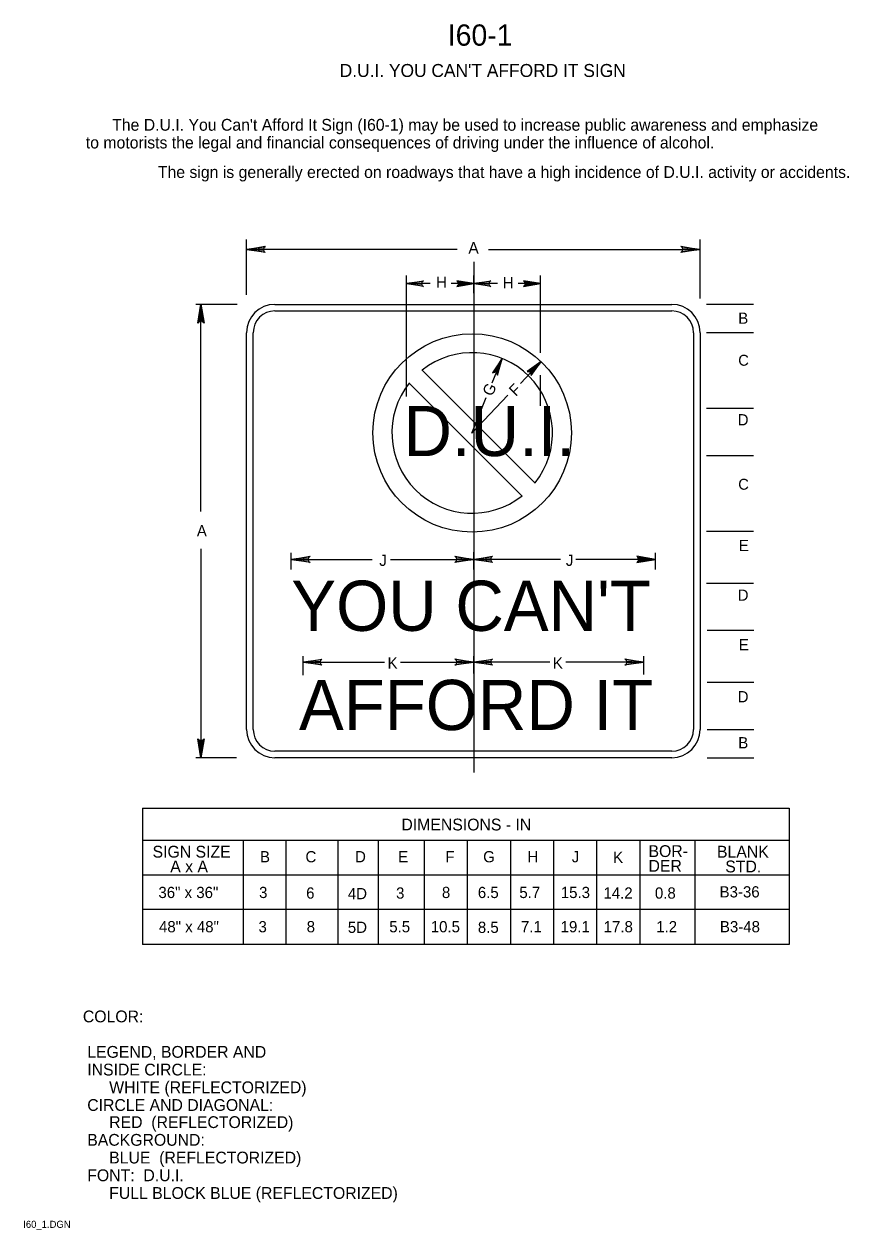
# Model space of a CAD drawing. Extents: x 0.013 to 0.187, y 0.004 to 0.259.
import ezdxf

# ---------------------------------------------------------------- set-up
doc = ezdxf.new("R2010")
doc.units = 0
doc.layers.add('1', color=7, linetype='Continuous')
doc.layers.add('3', color=7, linetype='Continuous')

# ---------------------------------------------------------------- blocks, each defined once
blk = doc.blocks.new('RARROW')
at = {"layer": '3'}
for p, q in [((-2.156, 0.28500000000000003), (-2.2665, 0.384625)), ((-2.2665, 0.384625), (0, 0)), ((0, 0), (-2.2665, -0.379125)), ((-2.156, 0.28500000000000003), (-2.075625, 0.12075)), ((0, 0), (-2.156, 0.28500000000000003)), ((-2.14975, -0.2705), (0, 0)), ((-2.075625, 0.12075), (0, 0)), ((0, 0), (-2.074, -0.108)), ((-2.2665, -0.379125), (-2.14975, -0.2705)), ((-2.074, -0.108), (-2.14975, -0.2705))]:
    blk.add_line(p, q, dxfattribs=at)

msp = doc.modelspace()

# ---------------------------------------------------------------- linework, layer by layer
at = {"layer": '1'}
for p, q in [((0.107875, 0.208875), (0.107875, 0.10075)), ((0.096875, 0.186), (0.120875, 0.162)), ((0.094125, 0.18325), (0.11812500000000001, 0.15925))]:
    msp.add_line(p, q, dxfattribs=at)
msp.add_circle((0.10754158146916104, 0.172648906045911), 0.021, dxfattribs=at)
for start, end in [(321.56815, 128.43185), (141.56815, 308.43185)]:
    msp.add_arc((0.10754158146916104, 0.172648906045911), 0.017, start, end, dxfattribs=at)
at = {"layer": '3'}
for p, q in [((0.059754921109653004, 0.20187213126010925), (0.059754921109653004, 0.21362213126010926)), ((0.15579158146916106, 0.20112213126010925), (0.15579158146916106, 0.21362213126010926)), ((0.104375, 0.2115), (0.059750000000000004, 0.2115)), ((0.111, 0.2115), (0.15575, 0.2115)), ((0.15579158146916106, 0.20149713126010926), (0.15579158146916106, 0.21012213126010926)), ((0.093625, 0.180375), (0.093625, 0.20600000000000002)), ((0.098625, 0.20425000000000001), (0.093625, 0.20425000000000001)), ((0.107875, 0.20425000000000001), (0.10312500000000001, 0.20425000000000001)), ((0.107875, 0.20225), (0.107875, 0.20600000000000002)), ((0.112875, 0.20425000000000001), (0.107875, 0.20425000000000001)), ((0.122, 0.20425000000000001), (0.11725000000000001, 0.20425000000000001)), ((0.122, 0.18962500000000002), (0.122, 0.20600000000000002)), ((0.05780174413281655, 0.19987213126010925), (0.049041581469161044, 0.19987213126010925)), ((0.050125, 0.156), (0.050125, 0.199875)), ((0.06579158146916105, 0.19987213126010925), (0.14979158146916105, 0.19987213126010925)), ((0.15712500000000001, 0.199875), (0.167125, 0.199875)), ((0.06579158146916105, 0.1984721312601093), (0.14979158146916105, 0.1984721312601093)), ((0.05979158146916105, 0.10987213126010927), (0.05979158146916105, 0.19387213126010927)), ((0.06119158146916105, 0.10987213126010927), (0.06119158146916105, 0.19387213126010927)), ((0.1543915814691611, 0.19387213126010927), (0.1543915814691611, 0.10987213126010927)), ((0.15579158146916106, 0.19387213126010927), (0.15579158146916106, 0.10987213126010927)), ((0.15712500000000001, 0.193875), (0.167125, 0.193875)), ((0.11175, 0.18325), (0.113875, 0.18837500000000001)), ((0.11775000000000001, 0.183125), (0.122125, 0.18775)), ((0.122, 0.178375), (0.122, 0.184875)), ((0.1075, 0.172625), (0.115125, 0.180625)), ((0.1075, 0.172625), (0.1105, 0.180125)), ((0.15712500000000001, 0.177875), (0.167125, 0.177875)), ((0.15712500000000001, 0.167875), (0.167125, 0.167875)), ((0.15712500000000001, 0.151875), (0.167125, 0.151875)), ((0.050125, 0.148125), (0.050125, 0.10387500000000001)), ((0.06925, 0.14375000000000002), (0.06925, 0.14725)), ((0.06925, 0.145875), (0.08637500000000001, 0.145875)), ((0.09025, 0.145875), (0.107875, 0.145875)), ((0.107875, 0.14375000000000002), (0.107875, 0.147375)), ((0.12625, 0.145875), (0.107875, 0.145875)), ((0.146375, 0.145875), (0.1295, 0.145875)), ((0.146375, 0.14375000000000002), (0.146375, 0.14725)), ((0.15712500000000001, 0.140875), (0.167125, 0.140875)), ((0.15729158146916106, 0.13087213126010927), (0.16716658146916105, 0.13087213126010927)), ((0.07175000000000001, 0.121375), (0.07175000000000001, 0.12537500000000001)), ((0.107875, 0.12175), (0.107875, 0.12537500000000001)), ((0.143875, 0.1215), (0.143875, 0.12537500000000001)), ((0.07175000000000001, 0.124125), (0.089, 0.124125)), ((0.092375, 0.124125), (0.107875, 0.124125)), ((0.124, 0.124125), (0.107875, 0.124125)), ((0.143875, 0.124125), (0.12737500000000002, 0.124125)), ((0.15729158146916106, 0.11987213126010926), (0.16716658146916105, 0.11987213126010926)), ((0.15729158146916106, 0.10987213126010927), (0.16716658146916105, 0.10987213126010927)), ((0.14979158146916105, 0.10527213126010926), (0.06579158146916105, 0.10527213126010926)), ((0.057666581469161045, 0.10387213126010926), (0.049041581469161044, 0.10387213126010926)), ((0.14979158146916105, 0.10387213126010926), (0.06579158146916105, 0.10387213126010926)), ((0.15729158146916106, 0.10387213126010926), (0.16716658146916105, 0.10387213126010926)), ((0.03775, 0.09325), (0.03775, 0.064375)), ((0.037761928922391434, 0.09325), (0.17463692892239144, 0.09325)), ((0.174625, 0.09325), (0.174625, 0.064375)), ((0.17463692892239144, 0.08637500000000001), (0.037761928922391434, 0.08637500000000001)), ((0.05905351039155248, 0.08637213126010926), (0.05905351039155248, 0.06437213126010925)), ((0.068125, 0.08637500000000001), (0.068125, 0.064375)), ((0.079125, 0.08637500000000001), (0.079125, 0.064375)), ((0.08762500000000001, 0.08637500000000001), (0.08762500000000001, 0.064375)), ((0.097375, 0.08637500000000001), (0.097375, 0.064375)), ((0.1065, 0.08637500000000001), (0.1065, 0.064375)), ((0.115625, 0.08637500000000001), (0.115625, 0.064375)), ((0.12475, 0.08637500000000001), (0.12475, 0.064375)), ((0.133875, 0.08637500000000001), (0.133875, 0.064375)), ((0.14305351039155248, 0.08637213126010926), (0.14305351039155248, 0.06437213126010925)), ((0.15467851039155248, 0.08637213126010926), (0.15467851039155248, 0.06437213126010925)), ((0.17463692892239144, 0.079), (0.037761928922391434, 0.079)), ((0.17463692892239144, 0.07175000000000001), (0.037761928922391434, 0.07175000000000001)), ((0.17463692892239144, 0.064375), (0.037761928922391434, 0.064375))]:
    msp.add_line(p, q, dxfattribs=at)
for centre, radius, start, end in [((0.06579158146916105, 0.1938721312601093), 0.006, 90, 180), ((0.14979158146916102, 0.1938721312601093), 0.006, 0, 90), ((0.06579158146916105, 0.1938721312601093), 0.0046, 90, 180), ((0.14979158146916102, 0.1938721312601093), 0.0046, 0, 90), ((0.06579158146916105, 0.1098721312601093), 0.006, 180, 270), ((0.06579158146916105, 0.1098721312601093), 0.0046, 180, 270), ((0.14979158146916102, 0.1098721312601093), 0.006, 270, 0), ((0.14979158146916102, 0.1098721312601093), 0.0046, 270, 0)]:
    msp.add_arc(centre, radius, start, end, dxfattribs=at)

# ---------------------------------------------------------------- block references
for p, xscale, yscale, rotation in [((0.059750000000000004, 0.2115), 0.0017647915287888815, 0.0017457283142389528, 180), ((0.093625, 0.20425000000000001), 0.0015883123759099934, 0.0015711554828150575, 180), ((0.107875, 0.20425000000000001), 0.0015883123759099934, 0.0015711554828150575, 180), ((0.050125, 0.199875), 0.0017647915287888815, 0.0017457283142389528, 90), ((0.113875, 0.18837500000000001), 0.0015883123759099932, -0.0015711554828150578, 65), ((0.122125, 0.18775), 0.0015883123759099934, -0.0015711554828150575, 44.99999999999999), ((0.06925, 0.145875), 0.0017647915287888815, 0.0017457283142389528, 180), ((0.107875, 0.145875), 0.0017647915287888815, 0.0017457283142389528, 180), ((0.07175000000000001, 0.124125), 0.0017647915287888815, 0.0017457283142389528, 180), ((0.107875, 0.124125), 0.0017647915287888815, 0.0017457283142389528, 180), ((0.050125, 0.10387500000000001), 0.0017647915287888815, 0.0017457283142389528, -90.00000000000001)]:
    msp.add_blockref('RARROW', p, dxfattribs=dict(at, xscale=xscale, yscale=yscale, rotation=rotation))
for p, xscale, yscale in [((0.15575, 0.2115), 0.0017647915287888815, 0.0017457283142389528), ((0.107875, 0.20425000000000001), 0.0015883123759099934, -0.0015711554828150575), ((0.122, 0.20425000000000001), 0.0015883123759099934, -0.0015711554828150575), ((0.107875, 0.145875), 0.0017647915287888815, 0.0017457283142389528), ((0.146375, 0.145875), 0.0017647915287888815, -0.0017457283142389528), ((0.107875, 0.124125), 0.0017647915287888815, 0.0017457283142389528), ((0.143875, 0.124125), 0.0017647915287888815, 0.0017457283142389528)]:
    msp.add_blockref('RARROW', p, dxfattribs=dict(at, xscale=xscale, yscale=yscale))

# ---------------------------------------------------------------- texts
at = {"layer": '1'}
for s, height, p in [('I60-1', 0.0045000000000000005, (0.10237500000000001, 0.254625)), ("D.U.I. YOU CAN'T AFFORD IT SIGN", 0.00275025, (0.0795, 0.248)), ("      The D.U.I. You Can't Afford It Sign (I60-1) may be used to increase public awareness and emphasize", 0.0024997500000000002, (0.025750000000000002, 0.236625)), ('to motorists the legal and financial consequences of driving under the influence of alcohol.', 0.0024997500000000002, (0.025750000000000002, 0.232875)), ('The sign is generally erected on roadways that have a high incidence of D.U.I. activity or accidents.', 0.0024997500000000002, (0.041, 0.226625)), ('COLOR:', 0.0024997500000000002, (0.025125, 0.047875)), (' LEGEND, BORDER AND', 0.0024997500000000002, (0.025125, 0.040375)), (' INSIDE CIRCLE:', 0.0024997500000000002, (0.025125, 0.036625)), ('      WHITE (REFLECTORIZED)', 0.0024997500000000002, (0.025125, 0.032875)), (' CIRCLE AND DIAGONAL:', 0.0024997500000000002, (0.025125, 0.029125)), ('      RED  (REFLECTORIZED)', 0.0024997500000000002, (0.025125, 0.025500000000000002)), (' BACKGROUND:', 0.0024997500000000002, (0.025125, 0.021750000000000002)), ('      BLUE  (REFLECTORIZED)', 0.0024997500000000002, (0.025125, 0.018000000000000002)), (' FONT:  D.U.I.', 0.0024997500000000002, (0.025125, 0.01425)), ('      FULL BLOCK BLUE (REFLECTORIZED)', 0.0024997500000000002, (0.025125, 0.0105)), ('I60_1.DGN', 0.0015, (0.0125, 0.004375))]:
    msp.add_text(s, height=height, dxfattribs=at).set_placement(p)
at = {"layer": '3'}
for s, height, p in [('A', 0.00243675, (0.10675, 0.210625)), ('H', 0.0023752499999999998, (0.099875, 0.203375)), ('H', 0.0023752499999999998, (0.114, 0.20325000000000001)), ('B', 0.0023752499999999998, (0.163875, 0.19575)), ('C', 0.0023175, (0.163875, 0.186875)), ('D.U.I.', 0.01062525, (0.093, 0.16775)), ('D', 0.0023752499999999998, (0.16375, 0.17425000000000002)), ('C', 0.0023175, (0.163875, 0.160625)), ('A', 0.0023752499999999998, (0.04925, 0.15075)), ('E', 0.0023752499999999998, (0.164, 0.147625)), ('J', 0.0023752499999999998, (0.08787500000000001, 0.1445)), ('J', 0.0023752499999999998, (0.12737500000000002, 0.1445)), ("YOU CAN'T", 0.01062525, (0.06925, 0.13075)), ('D', 0.0023752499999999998, (0.16375, 0.137125)), ('E', 0.0023752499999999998, (0.164, 0.12662500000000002)), ('K', 0.0023752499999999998, (0.089625, 0.12275)), ('K', 0.0023752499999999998, (0.124625, 0.12275)), ('AFFORD IT', 0.01062525, (0.07087500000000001, 0.10975)), ('D', 0.0023752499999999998, (0.16375, 0.115625)), ('B', 0.0023752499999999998, (0.163875, 0.105875)), ('DIMENSIONS - IN', 0.0024997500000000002, (0.09256253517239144, 0.0885)), ('SIGN SIZE', 0.0024997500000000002, (0.039875, 0.08275)), ('BOR-', 0.0024997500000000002, (0.144875, 0.082875)), ('BLANK', 0.0024997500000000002, (0.15937500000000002, 0.08275)), ('A x A', 0.0024997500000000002, (0.043625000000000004, 0.079625)), ('B', 0.0023752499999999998, (0.062625, 0.08175)), ('C', 0.0023752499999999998, (0.07225, 0.08175)), ('D', 0.0023752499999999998, (0.08275, 0.08175)), ('E', 0.0023752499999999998, (0.091875, 0.08175)), ('F', 0.0023752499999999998, (0.10187500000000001, 0.08175)), ('G', 0.0023752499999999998, (0.109875, 0.08175)), ('H', 0.0023752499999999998, (0.11925000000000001, 0.08175)), ('J', 0.0023752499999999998, (0.128625, 0.08175)), ('K', 0.0023752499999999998, (0.137375, 0.081625)), ('DER', 0.0024997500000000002, (0.144875, 0.07975)), ('STD.', 0.0024997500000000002, (0.161125, 0.079625)), ('36" x 36"', 0.0023752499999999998, (0.04112041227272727, 0.074187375)), ('3', 0.0023752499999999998, (0.06243161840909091, 0.074187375)), ('8', 0.0023752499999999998, (0.10113411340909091, 0.074187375)), ('6.5', 0.0023752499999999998, (0.1087463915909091, 0.074187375)), ('15.3', 0.0023752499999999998, (0.12630828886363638, 0.074187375)), ('B3-36', 0.0023752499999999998, (0.15992515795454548, 0.074312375)), ('6', 0.0023752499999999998, (0.07239706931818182, 0.074062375)), ('4D', 0.0023752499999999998, (0.08122156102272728, 0.073937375)), ('3', 0.0023752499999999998, (0.09143161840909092, 0.074062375)), ('5.7', 0.0023752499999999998, (0.11752914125, 0.074187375)), ('14.2', 0.0023752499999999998, (0.13532520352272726, 0.074062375)), ('0.8', 0.0023752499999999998, (0.14623055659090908, 0.074062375)), ('48" x 48"', 0.0023752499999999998, (0.04124541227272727, 0.06693737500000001)), ('3', 0.0023752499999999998, (0.06230661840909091, 0.06693737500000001)), ('8', 0.0023752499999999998, (0.07250911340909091, 0.06693737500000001)), ('5D', 0.0023752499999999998, (0.08122156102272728, 0.06681237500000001)), ('5.5', 0.0023752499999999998, (0.0899963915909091, 0.06693737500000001)), ('10.5', 0.0023752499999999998, (0.09877661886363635, 0.06693737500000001)), ('8.5', 0.0023752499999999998, (0.1087463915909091, 0.06681237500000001)), ('7.1', 0.0023752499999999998, (0.11786539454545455, 0.06693737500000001)), ('19.1', 0.0023752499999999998, (0.12627062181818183, 0.06693737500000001)), ('17.8', 0.0023752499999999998, (0.13538578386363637, 0.06693737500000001)), ('1.2', 0.0023752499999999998, (0.14651090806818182, 0.06693737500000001)), ('B3-48', 0.0023752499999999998, (0.15998846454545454, 0.06693737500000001))]:
    msp.add_text(s, height=height, dxfattribs=at).set_placement(p)
for s, rotation, p in [('G', 65, (0.11175, 0.18025)), ('F', 45, (0.11675, 0.18025))]:
    msp.add_text(s, height=0.0023752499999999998, rotation=rotation, dxfattribs=at).set_placement(p)

doc.saveas('drawing.dxf')
